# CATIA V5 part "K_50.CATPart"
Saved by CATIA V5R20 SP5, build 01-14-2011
Part number: 50
Bounding box of the stored display mesh (mm): x -15 to 15, y -15 to 15, z -20 to 87
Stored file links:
  G:\Khaled_CFAO_2011\ST2M\ST2M_GR1\lpierredon\Khaled\CAD_thinkMOTION\K_50.CATPart
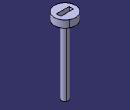
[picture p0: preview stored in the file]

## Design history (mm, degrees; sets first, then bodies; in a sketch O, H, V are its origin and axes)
Body1 (main body)
  Sketch1 on yz-plane, origin (0, 0, 0), H (0, 1, 0), V (0, 0, 1)
    line L1 (0, -20) -> (0, 87)
    point P1 (0, -20)
    line L2 (0, 87) -> (15, 87)
    line L3 (15, 87) -> (15, 77)
    line L4 (15, 77) -> (5, 77)
    line L5 (5, 77) -> (5, -20)
    line L6 (5, -20) -> (0, -20)
    length L3 = 10
    length L5 = 97
    distance L5 L1 = 5
    length L4 = 10
    coincidence: P1 V
    vertical: L1 V, L3 V, L5 V
    horizontal: L2 H, L4 H, L6 H
  Shaft1: profile Sketch1, axis Sketch1.L1, angle 360
  Sketch2 on face of Shaft1 from Sketch1.L2, origin (0, 0, 87), H (1, 0, 0), V (0, 1, 0)
    line L1 (-9, 3) -> (9, 3)
    line L2 (9, 3) -> (9, -3)
    line L3 (9, -3) -> (-9, -3)
    line L4 (-9, -3) -> (-9, 3)
    horizontal: L1 H, L3 H
    vertical: L2 V, L4 V
    symmetry: L1 L3 H, L2 L4 V
  Pocket1: profile Sketch2, direction (0, 0, -1), length 8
